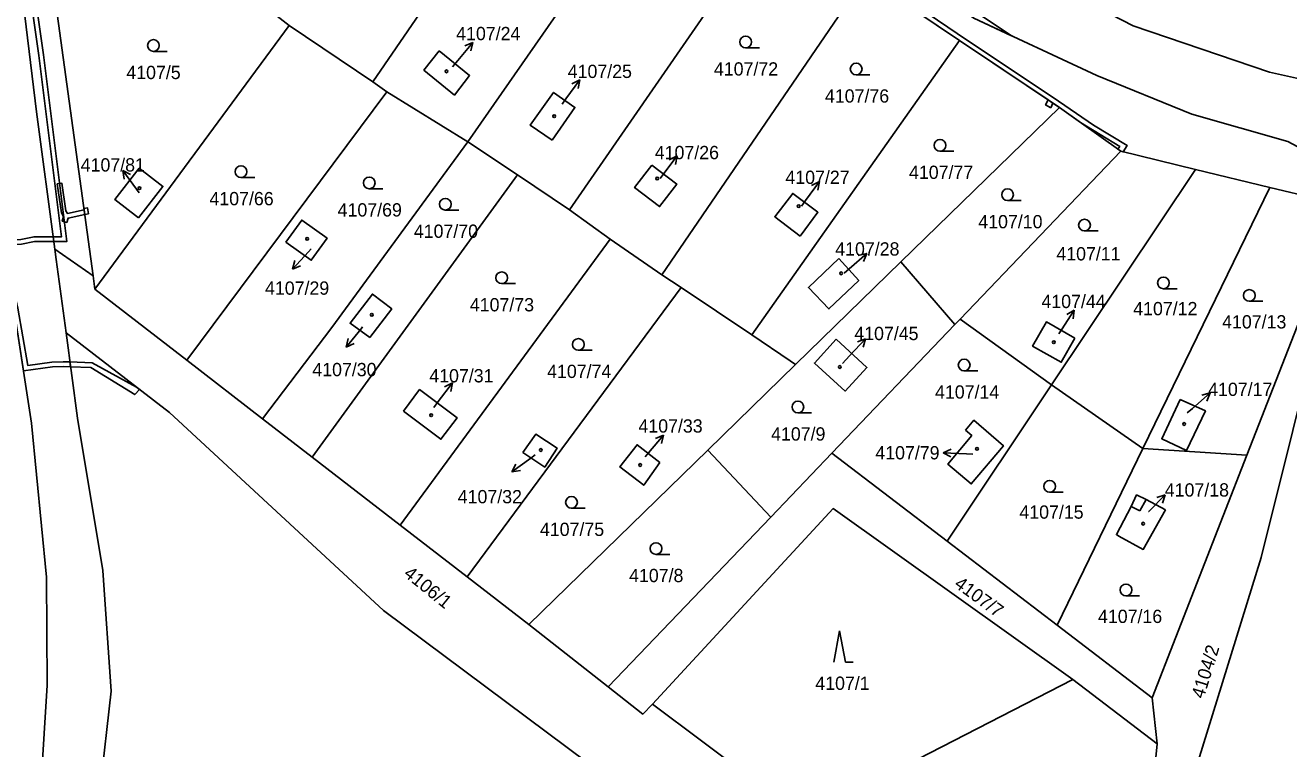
# Model space of a CAD drawing. Extents: x -869103 to -863415, y -1015889 to -1012477.
# Drawn here: x -865887.9 to -865726.2, y -1015523.3 to -1015430.7 of the extents above; entities that cross this region are included whole.
import ezdxf

# ---------------------------------------------------------------- set-up
doc = ezdxf.new("R2010")
doc.units = 0
for name, color, linetype in [('Hranice parcel', 7, 'Continuous'), ('Parcelní čísla', 7, 'Continuous'), ('Pop  PČ popisy', 7, 'Continuous'), ('Vnitřní kresba', 7, 'Continuous'), ('Věcná břemena k části', 7, 'Continuous'), ('Značky budov', 7, 'Continuous'), ('Značky kultur', 7, 'Continuous')]:
    doc.layers.add(name, color=color, linetype=linetype)

msp = doc.modelspace()

# ---------------------------------------------------------------- linework, layer by layer
at = {"layer": 'Hranice parcel'}
for p, q in [((-865843.43, -1015437.95), (-865817.34, -1015399.74)), ((-865831.29, -1015445.63), (-865805.08, -1015407.99)), ((-865818.26, -1015454.37), (-865792.19, -1015416.64)), ((-865879.25, -1015462.82), (-865884.82, -1015422.02)), ((-865806.47, -1015462.69), (-865780.43, -1015424.55)), ((-865768.36, -1015432.66), (-865780.43, -1015424.55)), ((-865854.17, -1015430.76), (-865856.09, -1015429.25)), ((-865766.53, -1015429.83), (-865750.77, -1015437.18)), ((-865879.02, -1015464.53), (-865854.17, -1015430.76)), ((-865843.43, -1015437.95), (-865854.17, -1015430.76)), ((-865728.67, -1015436.75), (-865746.12, -1015430.79)), ((-865794.94, -1015470.36), (-865768.36, -1015432.66)), ((-865755.56, -1015441.26), (-865768.36, -1015432.66)), ((-865714.67, -1015439.82), (-865728.67, -1015436.75)), ((-865841.66, -1015439.23), (-865843.43, -1015437.95)), ((-865867.26, -1015473.61), (-865841.66, -1015439.23)), ((-865841.66, -1015439.23), (-865831.29, -1015445.63)), ((-865755.56, -1015441.26), (-865775.85, -1015461.03)), ((-865747.71, -1015446.86), (-865755.56, -1015441.26)), ((-865884.14, -1015459.37), (-865886.49, -1015441.79)), ((-865824.93, -1015449.89), (-865831.29, -1015445.63)), ((-865768.28, -1015468.36), (-865747.71, -1015446.86)), ((-865738.17, -1015449.18), (-865747.71, -1015446.86)), ((-865756.57, -1015476.75), (-865738.17, -1015449.18)), ((-865728.62, -1015451.49), (-865738.17, -1015449.18)), ((-865851.2, -1015486.03), (-865824.93, -1015449.89)), ((-865824.93, -1015449.89), (-865818.26, -1015454.37)), ((-865744.87, -1015484.91), (-865728.62, -1015451.49)), ((-865719.11, -1015453.8), (-865728.62, -1015451.49)), ((-865818.26, -1015454.37), (-865813.06, -1015458.11)), ((-865731.58, -1015485.75), (-865719.11, -1015453.8)), ((-865879.25, -1015462.82), (-865884.14, -1015459.37)), ((-865839.95, -1015494.71), (-865813.06, -1015458.11)), ((-865813.06, -1015458.11), (-865806.47, -1015462.69)), ((-865775.85, -1015461.03), (-865789.34, -1015474.17)), ((-865768.94, -1015469.05), (-865775.85, -1015461.03)), ((-865879.02, -1015464.53), (-865879.25, -1015462.82)), ((-865831.38, -1015501.34), (-865803.97, -1015464.28)), ((-865803.97, -1015464.28), (-865806.47, -1015462.69)), ((-865794.94, -1015470.36), (-865803.97, -1015464.28)), ((-865887.15, -1015481.68), (-865889.72, -1015464.71)), ((-865879.02, -1015464.53), (-865867.26, -1015473.61)), ((-865784.69, -1015485.51), (-865768.94, -1015469.05)), ((-865768.94, -1015469.05), (-865768.28, -1015468.36)), ((-865768.28, -1015468.36), (-865756.57, -1015476.75)), ((-865882.71, -1015470.11), (-865881.27, -1015481.01)), ((-865867.26, -1015473.61), (-865857.56, -1015481.11)), ((-865789.34, -1015474.17), (-865800.56, -1015485.11)), ((-865769.93, -1015496.78), (-865756.57, -1015476.75)), ((-865756.57, -1015476.75), (-865744.87, -1015484.91)), ((-865857.56, -1015481.11), (-865851.2, -1015486.03)), ((-865800.56, -1015485.11), (-865823.48, -1015507.44)), ((-865792.51, -1015493.68), (-865800.56, -1015485.11)), ((-865755.87, -1015507.53), (-865744.87, -1015484.91)), ((-865744.87, -1015484.91), (-865731.58, -1015485.75)), ((-865851.2, -1015486.03), (-865839.95, -1015494.71)), ((-865792.51, -1015493.68), (-865784.69, -1015485.51)), ((-865784.69, -1015485.51), (-865769.93, -1015496.78)), ((-865743.71, -1015516.82), (-865731.58, -1015485.75)), ((-865839.95, -1015494.71), (-865831.38, -1015501.34)), ((-865813.31, -1015515.41), (-865792.51, -1015493.68)), ((-865769.93, -1015496.78), (-865755.87, -1015507.53)), ((-865831.38, -1015501.34), (-865823.48, -1015507.44)), ((-865823.48, -1015507.44), (-865813.31, -1015515.41)), ((-865755.87, -1015507.53), (-865743.71, -1015516.82)), ((-865787.68, -1015531.83), (-865753.86, -1015514.46)), ((-865753.86, -1015514.46), (-865743.07, -1015522.7)), ((-865788.19, -1015532.18), (-865807.64, -1015517.64)), ((-865743.71, -1015516.82), (-865743.07, -1015522.7)), ((-865743.07, -1015522.7), (-865745.89, -1015551.01))]:
    msp.add_line(p, q, dxfattribs=at)
for points in [[(-865886.49, -1015441.79), (-865896.67, -1015358.6), (-865897.99, -1015347.11), (-865903.61, -1015335.52)], [(-865746.12, -1015430.79), (-865766.69, -1015420.18), (-865772.13, -1015416.66), (-865801.59, -1015397.55), (-865804.2, -1015395.73)], [(-865834.94, -1015434.02), (-865836.92, -1015436.46), (-865833, -1015439.66), (-865831.07, -1015437.17), (-865834.94, -1015434.02)], [(-865750.77, -1015437.18), (-865738.61, -1015442.09), (-865726.33, -1015445.62), (-865717.62, -1015450.27)], [(-865820.48, -1015445.42), (-865817.58, -1015441.25), (-865820.31, -1015439.32), (-865823.29, -1015443.52), (-865820.48, -1015445.42)], [(-865857.56, -1015481.11), (-865848.7, -1015469.4), (-865831.29, -1015445.63)], [(-865873.45, -1015455.39), (-865876.47, -1015453.04), (-865873.35, -1015449.01), (-865870.31, -1015451.35), (-865873.45, -1015455.39)], [(-865807.74, -1015448.62), (-865809.94, -1015451.51), (-865806.74, -1015453.93), (-865804.54, -1015451.06), (-865807.74, -1015448.62)], [(-865717.62, -1015450.27), (-865729.73, -1015498.87), (-865745.89, -1015551.01)], [(-865788.76, -1015457.71), (-865786.48, -1015454.66), (-865789.7, -1015452.25), (-865792, -1015455.24), (-865788.76, -1015457.71)], [(-865854.57, -1015458.48), (-865851.34, -1015460.81), (-865849.3, -1015458), (-865852.54, -1015455.67), (-865854.57, -1015458.48)], [(-865884.14, -1015459.37), (-865883.96, -1015460.71), (-865882.71, -1015470.11)], [(-865783.82, -1015460.59), (-865787.7, -1015464.31), (-865785.08, -1015467.04), (-865781.26, -1015463.38), (-865783.82, -1015460.59)], [(-865843.83, -1015470.69), (-865841.03, -1015467.03), (-865843.5, -1015465.14), (-865846.37, -1015468.88), (-865843.83, -1015470.69)], [(-865753.58, -1015470.77), (-865755.34, -1015473.87), (-865759, -1015471.79), (-865757.23, -1015468.7), (-865753.58, -1015470.77)], [(-865750.44, -1015576.59), (-865773.08, -1015561.48), (-865795.05, -1015540.71), (-865842.08, -1015505.65), (-865869.48, -1015480.31), (-865882.71, -1015470.11)], [(-865789.34, -1015474.17), (-865790.05, -1015473.69), (-865794.94, -1015470.36)], [(-865784.14, -1015470.93), (-865780.21, -1015474.53), (-865782.98, -1015477.56), (-865786.92, -1015473.97), (-865784.14, -1015470.93)], [(-865839.54, -1015480.13), (-865834.73, -1015483.73), (-865832.66, -1015480.96), (-865837.47, -1015477.36), (-865839.54, -1015480.13)], [(-865740.1, -1015478.65), (-865736.89, -1015480.09), (-865739.29, -1015485.17), (-865742.48, -1015483.65), (-865740.1, -1015478.65)], [(-865887.36, -1015535.4), (-865885.92, -1015527.56), (-865885.14, -1015515.21), (-865885.23, -1015501.36), (-865887.15, -1015481.68)], [(-865881.27, -1015481.01), (-865878.01, -1015500.53), (-865876.93, -1015515.95), (-865878.33, -1015528.44), (-865879.2, -1015537.17)], [(-865767.61, -1015482.55), (-865766.51, -1015481.29), (-865762.74, -1015484.55), (-865766.86, -1015489.43), (-865769.85, -1015486.9), (-865766.78, -1015483.25), (-865767.61, -1015482.55)], [(-865824.26, -1015485.42), (-865821.44, -1015487.29), (-865819.87, -1015484.85), (-865822.6, -1015483.09), (-865824.26, -1015485.42)], [(-865806.7, -1015486.69), (-865809.63, -1015484.43), (-865811.82, -1015487.27), (-865808.77, -1015489.61), (-865806.7, -1015486.69)], [(-865741.98, -1015492.77), (-865744.84, -1015497.83), (-865747.95, -1015496.11), (-865748.28, -1015495.92), (-865746.37, -1015492.32), (-865745.69, -1015490.84), (-865744.46, -1015491.44), (-865741.98, -1015492.77)], [(-865753.86, -1015514.46), (-865784.54, -1015492.59), (-865807.64, -1015517.64)], [(-865807.64, -1015517.64), (-865808.87, -1015518.89), (-865813.31, -1015515.41)]]:
    msp.add_lwpolyline(points, dxfattribs=at)
at = {"layer": 'Pop  PČ popisy'}
for p, q in [((-865832.58, -1015435.23), (-865830.65, -1015432.93)), ((-865830.65, -1015432.93), (-865831.68, -1015433.38)), ((-865830.65, -1015432.93), (-865830.91, -1015434.02)), ((-865833.27, -1015436.07), (-865832.58, -1015435.23)), ((-865818.73, -1015440.15), (-865816.97, -1015437.72)), ((-865816.97, -1015437.72), (-865817.96, -1015438.24)), ((-865816.97, -1015437.72), (-865817.15, -1015438.83)), ((-865819.23, -1015440.83), (-865818.73, -1015440.15)), ((-865806.32, -1015449.86), (-865804.51, -1015447.46)), ((-865804.51, -1015447.46), (-865805.52, -1015447.96)), ((-865804.51, -1015447.46), (-865804.72, -1015448.56)), ((-865873.69, -1015451.73), (-865875.45, -1015449.3)), ((-865875.45, -1015449.3), (-865874.46, -1015449.82)), ((-865875.45, -1015449.3), (-865875.27, -1015450.41)), ((-865806.69, -1015450.35), (-865806.32, -1015449.86)), ((-865788.05, -1015453.16), (-865786.29, -1015450.73)), ((-865786.29, -1015450.73), (-865787.28, -1015451.25)), ((-865786.29, -1015450.73), (-865786.47, -1015451.84)), ((-865873.36, -1015452.19), (-865873.69, -1015451.73)), ((-865788.58, -1015453.88), (-865788.05, -1015453.16)), ((-865851.32, -1015459.33), (-865851.69, -1015459.73)), ((-865851.69, -1015459.73), (-865853.74, -1015461.93)), ((-865853.74, -1015461.93), (-865853.42, -1015460.85)), ((-865782.49, -1015461.91), (-865780.22, -1015459.94)), ((-865780.22, -1015459.94), (-865781.31, -1015460.22)), ((-865780.22, -1015459.94), (-865780.65, -1015460.98)), ((-865853.74, -1015461.93), (-865852.69, -1015461.53)), ((-865783.14, -1015462.48), (-865782.49, -1015461.91)), ((-865755.3, -1015469.71), (-865753.67, -1015467.19)), ((-865753.67, -1015467.19), (-865754.63, -1015467.76)), ((-865753.67, -1015467.19), (-865753.79, -1015468.31)), ((-865844.96, -1015469.6), (-865846.85, -1015471.93)), ((-865844.75, -1015469.34), (-865844.96, -1015469.6)), ((-865755.64, -1015470.24), (-865755.3, -1015469.71)), ((-865846.85, -1015471.93), (-865846.61, -1015470.84)), ((-865846.85, -1015471.93), (-865845.83, -1015471.47)), ((-865782.43, -1015473.06), (-865780.38, -1015470.86)), ((-865780.38, -1015470.86), (-865781.43, -1015471.26)), ((-865780.38, -1015470.86), (-865780.7, -1015471.94)), ((-865783.33, -1015474.03), (-865782.43, -1015473.06)), ((-865835.07, -1015478.9), (-865833.26, -1015476.5)), ((-865833.26, -1015476.5), (-865834.27, -1015477)), ((-865833.26, -1015476.5), (-865833.47, -1015477.6)), ((-865738.54, -1015479.77), (-865736.28, -1015477.8)), ((-865736.28, -1015477.8), (-865737.36, -1015478.08)), ((-865736.28, -1015477.8), (-865736.7, -1015478.84)), ((-865835.66, -1015479.67), (-865835.07, -1015478.9)), ((-865739.21, -1015480.36), (-865738.54, -1015479.77)), ((-865808.18, -1015485.48), (-865806.25, -1015483.18)), ((-865806.25, -1015483.18), (-865807.28, -1015483.63)), ((-865806.25, -1015483.18), (-865806.51, -1015484.27)), ((-865770.45, -1015485.44), (-865769.42, -1015484.99)), ((-865823.23, -1015486.13), (-865825.66, -1015487.89)), ((-865825.66, -1015487.89), (-865825.14, -1015486.9)), ((-865822.69, -1015485.73), (-865823.23, -1015486.13)), ((-865808.6, -1015485.98), (-865808.18, -1015485.48)), ((-865767.45, -1015485.6), (-865770.45, -1015485.44)), ((-865770.45, -1015485.44), (-865769.47, -1015485.99)), ((-865766.65, -1015485.64), (-865767.45, -1015485.6)), ((-865825.66, -1015487.89), (-865824.55, -1015487.71)), ((-865744.14, -1015492.95), (-865742.02, -1015490.83)), ((-865742.02, -1015490.83), (-865743.08, -1015491.18)), ((-865742.02, -1015490.83), (-865742.37, -1015491.89)), ((-865744.15, -1015492.96), (-865744.14, -1015492.95))]:
    msp.add_line(p, q, dxfattribs=at)
at = {"layer": 'Vnitřní kresba'}
for p, q in [((-865745.27, -1015492.9), (-865744.46, -1015491.44)), ((-865746.37, -1015492.32), (-865745.27, -1015492.9))]:
    msp.add_line(p, q, dxfattribs=at)
at = {"layer": 'Věcná břemena k části'}
for points in [[(-865799.12, -1015404.79), (-865801.89, -1015403.05), (-865805.73, -1015402.03), (-865808.16, -1015401.11), (-865805.32, -1015403.02), (-865804.93, -1015403.29), (-865802.28, -1015403.99), (-865800.12, -1015405.34), (-865800.13, -1015406.66), (-865780.39, -1015420.54), (-865766.53, -1015429.83), (-865761.71, -1015432.08), (-865773.2, -1015424.33), (-865777.53, -1015421.51), (-865789.29, -1015413.43), (-865798.73, -1015407.3), (-865799.13, -1015406.16)], [(-865756.66, -1015441.3), (-865756.4, -1015440.7), (-865757, -1015440.29), (-865757.34, -1015440.92)], [(-865883.85, -1015451.03), (-865883.29, -1015454.72), (-865883.05, -1015455.2), (-865883.2, -1015455.8), (-865882.63, -1015455.97), (-865882.46, -1015455.41), (-865880.32, -1015454.96), (-865880.4, -1015454.37), (-865882.53, -1015454.81), (-865882.75, -1015454.47), (-865883.26, -1015450.94)], [(-865880.4, -1015454.37), (-865880.32, -1015454.96), (-865879.85, -1015454.86), (-865879.96, -1015454.11), (-865880.43, -1015454.18)], [(-865890.72, -1015458.92), (-865888.43, -1015458.76), (-865886.74, -1015458.41), (-865884.27, -1015458.4), (-865884.35, -1015457.8), (-865886.8, -1015457.81), (-865888.51, -1015458.16), (-865890.82, -1015458.32)], [(-865890.42, -1015460.64), (-865889.72, -1015464.71), (-865888.17, -1015474.97), (-865884.47, -1015474.44), (-865883.09, -1015474.39), (-865882.14, -1015474.43), (-865882.22, -1015473.83), (-865883.09, -1015473.79), (-865884.53, -1015473.84), (-865887.61, -1015474.28), (-865888.9, -1015466.94), (-865890.05, -1015461.94)], [(-865879.39, -1015473.95), (-865882.22, -1015473.83), (-865882.14, -1015474.43), (-865879.55, -1015474.55), (-865873.93, -1015478.01), (-865873.32, -1015477.35), (-865873.71, -1015477.05)]]:
    msp.add_lwpolyline(points, close=True, dxfattribs=at)
for points in [[(-865888.17, -1015420.83), (-865886.19, -1015434.6), (-865884.56, -1015447.55), (-865883.28, -1015457.79), (-865884.35, -1015457.8), (-865884.27, -1015458.4), (-865882.6, -1015458.39), (-865883.96, -1015447.47), (-865885.59, -1015434.52), (-865887.57, -1015420.75), (-865889.46, -1015405.8)], [(-865780.43, -1015424.55), (-865768.36, -1015432.66), (-865757, -1015440.29), (-865756.4, -1015440.7), (-865755.56, -1015441.26), (-865752.88, -1015443.17), (-865747.85, -1015446.25), (-865748.09, -1015446.59), (-865747.71, -1015446.86), (-865747.4, -1015446.94), (-865746.88, -1015446.14), (-865751.2, -1015443.5), (-865756.38, -1015439.96), (-865767.33, -1015432.7), (-865775.02, -1015427.45)]]:
    msp.add_lwpolyline(points, dxfattribs=at)
at = {"layer": 'Značky budov'}
for centre in [(-865834.02, -1015436.63), (-865820.23, -1015442.38), (-865807.05, -1015450.35), (-865873.33, -1015451.57), (-865788.94, -1015453.88), (-865851.87, -1015458.08), (-865783.5, -1015462.48), (-865843.59, -1015467.79), (-865756.28, -1015471.3), (-865783.68, -1015474.47), (-865835.98, -1015480.65), (-865739.6, -1015481.77), (-865821.95, -1015485.1), (-865766.12, -1015484.96), (-865809.22, -1015487.02), (-865744.86, -1015494.53)]:
    msp.add_circle(centre, 0.175, dxfattribs=at)
at = {"layer": 'Značky kultur'}
for p, q in [((-865871.53, -1015434.07), (-865869.78, -1015434.07)), ((-865795.72, -1015433.62), (-865793.97, -1015433.62)), ((-865781.58, -1015437.08), (-865779.83, -1015437.08)), ((-865770.85, -1015446.85), (-865769.1, -1015446.85)), ((-865860.32, -1015450.22), (-865858.57, -1015450.22)), ((-865843.91, -1015451.66), (-865842.16, -1015451.66)), ((-865834.17, -1015454.39), (-865832.42, -1015454.39)), ((-865762.2, -1015453.17), (-865760.45, -1015453.17)), ((-865752.36, -1015457.06), (-865750.61, -1015457.06)), ((-865826.95, -1015463.8), (-865825.2, -1015463.8)), ((-865742.25, -1015464.46), (-865740.5, -1015464.46)), ((-865731.26, -1015466.06), (-865729.51, -1015466.06)), ((-865817.14, -1015472.33), (-865815.39, -1015472.33)), ((-865767.76, -1015474.97), (-865766.01, -1015474.97)), ((-865789.04, -1015480.34), (-865787.29, -1015480.34)), ((-865756.82, -1015490.5), (-865755.07, -1015490.5)), ((-865818.02, -1015492.55), (-865816.27, -1015492.55)), ((-865807.2, -1015498.46), (-865805.45, -1015498.46)), ((-865747.05, -1015503.76), (-865745.3, -1015503.76)), ((-865783.7, -1015508.25), (-865784.45, -1015512.25)), ((-865782.95, -1015512.25), (-865783.7, -1015508.25)), ((-865782.95, -1015512.25), (-865781.95, -1015512.25))]:
    msp.add_line(p, q, dxfattribs=at)
for centre in [(-865871.53, -1015433.32), (-865795.72, -1015432.87), (-865781.58, -1015436.33), (-865770.85, -1015446.1), (-865860.32, -1015449.47), (-865843.91, -1015450.91), (-865834.17, -1015453.64), (-865762.2, -1015452.42), (-865752.36, -1015456.31), (-865826.95, -1015463.05), (-865742.25, -1015463.71), (-865731.26, -1015465.31), (-865817.14, -1015471.58), (-865767.76, -1015474.22), (-865789.04, -1015479.59), (-865756.82, -1015489.75), (-865818.02, -1015491.8), (-865807.2, -1015497.71), (-865747.05, -1015503.01)]:
    msp.add_circle(centre, 0.75, dxfattribs=at)

# ---------------------------------------------------------------- texts
at = {"layer": 'Parcelní čísla'}
for s, p in [('4107/24', (-865832.78, -1015432.64)), ('4107/5', (-865875, -1015437.62)), ('4107/25', (-865818.5, -1015437.48)), ('4107/72', (-865799.79, -1015437.17)), ('4107/76', (-865785.58, -1015440.63)), ('4107/26', (-865807.36, -1015447.87)), ('4107/81', (-865880.84, -1015449.45)), ('4107/27', (-865790.64, -1015451.04)), ('4107/77', (-865774.82, -1015450.4)), ('4107/66', (-865864.36, -1015453.77)), ('4107/69', (-865847.95, -1015455.21)), ('4107/70', (-865838.2, -1015457.94)), ('4107/10', (-865765.95, -1015456.72)), ('4107/28', (-865784.26, -1015460.21)), ('4107/11', (-865755.96, -1015460.83)), ('4107/29', (-865857.25, -1015465.22)), ('4107/73', (-865831.03, -1015467.35)), ('4107/44', (-865757.87, -1015466.93)), ('4107/12', (-865746.12, -1015467.85)), ('4107/13', (-865734.74, -1015469.54)), ('4107/45', (-865781.82, -1015471.03)), ('4107/30', (-865851.19, -1015475.65)), ('4107/31', (-865836.22, -1015476.44)), ('4107/74', (-865821.14, -1015475.88)), ('4107/14', (-865771.49, -1015478.52)), ('4107/17', (-865736.53, -1015478.18)), ('4107/33', (-865809.45, -1015482.87)), ('4107/9', (-865792.47, -1015483.89)), ('4107/79', (-865779.13, -1015486.3)), ('4107/32', (-865832.58, -1015491.92)), ('4107/18', (-865742.08, -1015491.06)), ('4107/15', (-865760.69, -1015493.89)), ('4107/75', (-865822.06, -1015496.1)), ('4107/8', (-865810.65, -1015502.01)), ('4107/16', (-865750.63, -1015507.24)), ('4107/1', (-865786.81, -1015515.8))]:
    msp.add_text(s, height=1.7, dxfattribs=at).set_placement(p)
for s, rotation, p in [('4106/1', 321, (-865839.62, -1015501.14)), ('4107/7', 324, (-865769.15, -1015502.53)), ('4104/2', 73, (-865737.1, -1015517.02))]:
    msp.add_text(s, height=1.7, rotation=rotation, dxfattribs=at).set_placement(p)

doc.saveas('drawing.dxf')
